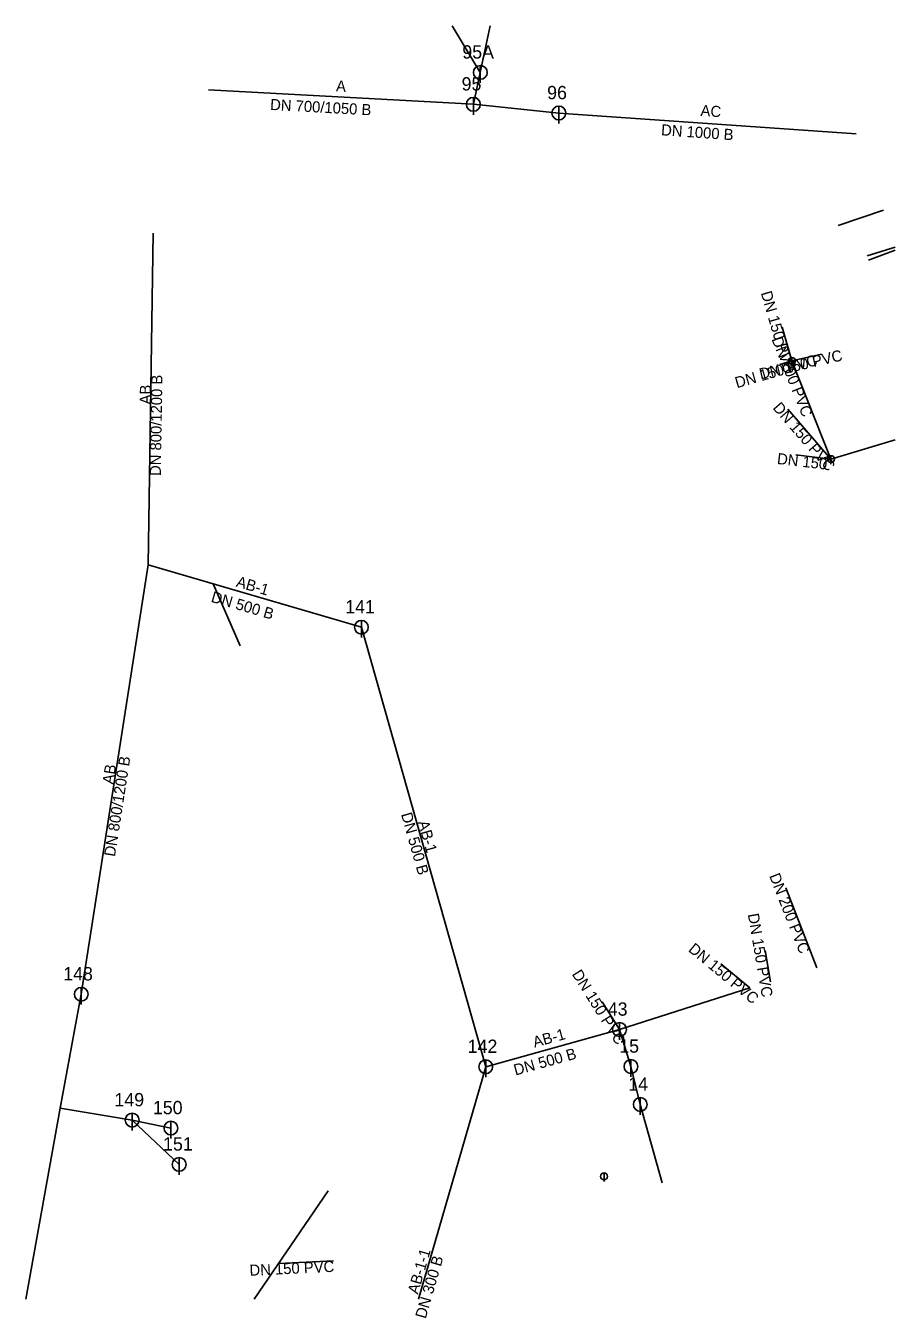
# Model space of a CAD drawing. Extents: x -444516 to -444390, y -1121153 to -1120965.
import ezdxf

# ---------------------------------------------------------------- set-up
doc = ezdxf.new("R2010")
doc.units = 0
for name, color, linetype in [('_pripojka_kanal_destova_priblizne_', 7, 'Continuous'), ('_pripojka_kanal_jednotna_priblizne_', 7, 'Continuous'), ('_pripojka_kanal_splaskova_priblizne_', 7, 'Continuous'), ('_stoka_jednotna_smvak_prevzato_z_dokumentace_', 7, 'Continuous'), ('Default', 7, 'Continuous'), ('MoLevel 119', 7, 'Continuous'), ('MoLevel 120', 7, 'Continuous'), ('MoLevel 124', 7, 'Continuous'), ('MoLevel 128', 7, 'Continuous'), ('MoLevel 57', 7, 'Continuous'), ('MoLevel 60', 7, 'Continuous'), ('MoLevel 68', 7, 'Continuous'), ('MoLevel 69', 7, 'Continuous')]:
    doc.layers.add(name, color=color, linetype=linetype)

# ---------------------------------------------------------------- blocks, each defined once
blk = doc.blocks.new('_sachta_kanal_prip_')
at = {"layer": 'Default'}
blk.add_line((0, 0.00005), (0, -0.000075), dxfattribs=at)
blk.add_circle((0, 0), 0.00005, dxfattribs=at)
blk = doc.blocks.new('_sachta_kanal_prevzato_z_dokumentace_')
at = {"layer": 'Default'}
blk.add_line((0, 0.00005), (0, -0.000075), dxfattribs=at)
blk.add_circle((0, 0), 0.00005, dxfattribs=at)

msp = doc.modelspace()

# ---------------------------------------------------------------- linework, layer by layer
at = {"layer": '_pripojka_kanal_destova_priblizne_'}
for p, q in [((-444453.97, -1120965.24), (-444449.9, -1120971.98)), ((-444405.37, -1121020.79), (-444399.11, -1121028.01))]:
    msp.add_line(p, q, dxfattribs=at)
at = {"layer": '_pripojka_kanal_jednotna_priblizne_'}
for p, q in [((-444398.04, -1120994.19), (-444391.52, -1120991.95)), ((-444393.86, -1120998.56), (-444389.81, -1120997.31)), ((-444393.69, -1120999.17), (-444389.81, -1120997.76)), ((-444399.11, -1121028.01), (-444389.81, -1121025.21)), ((-444484.67, -1121055.09), (-444488.59, -1121046.11)), ((-444405.66, -1121090.17), (-444401.13, -1121101.74)), ((-444408.63, -1121099.25), (-444407.86, -1121103.76)), ((-444415.04, -1121101.17), (-444410.85, -1121104.65)), ((-444432.26, -1121106.67), (-444429.74, -1121110.68)), ((-444471.95, -1121134.05), (-444482.65, -1121149.76)), ((-444471.15, -1121144.19), (-444479.12, -1121144.57))]:
    msp.add_line(p, q, dxfattribs=at)
at = {"layer": '_pripojka_kanal_splaskova_priblizne_'}
for p, q in [((-444406.17, -1121008.92), (-444404.76, -1121013.79)), ((-444400.5, -1121012.8), (-444404.76, -1121013.79)), ((-444406.5, -1121014.29), (-444404.76, -1121013.79)), ((-444404.76, -1121013.79), (-444399.11, -1121028.01)), ((-444404.21, -1121027.42), (-444399.11, -1121028.01))]:
    msp.add_line(p, q, dxfattribs=at)
at = {"layer": '_stoka_jednotna_smvak_prevzato_z_dokumentace_'}
for p, q in [((-444448.46, -1120965.24), (-444449.9, -1120971.98)), ((-444449.9, -1120971.98), (-444450.91, -1120976.61)), ((-444450.91, -1120976.61), (-444489.29, -1120974.53)), ((-444438.52, -1120977.87), (-444450.91, -1120976.61)), ((-444395.45, -1120980.88), (-444438.52, -1120977.87)), ((-444498.04, -1121043.34), (-444497.27, -1120995.3)), ((-444507.71, -1121105.57), (-444498.04, -1121043.34)), ((-444467.13, -1121052.39), (-444498.04, -1121043.34)), ((-444449.12, -1121116.07), (-444467.13, -1121052.39)), ((-444410.85, -1121104.65), (-444429.74, -1121110.68)), ((-444510.74, -1121122.07), (-444507.71, -1121105.57)), ((-444429.74, -1121110.68), (-444449.12, -1121116.07)), ((-444428.08, -1121116.04), (-444429.74, -1121110.68)), ((-444458.88, -1121149.76), (-444449.12, -1121116.07)), ((-444426.73, -1121121.54), (-444428.08, -1121116.04)), ((-444423.57, -1121132.89), (-444426.73, -1121121.54)), ((-444515.73, -1121149.76), (-444510.74, -1121122.07)), ((-444500.33, -1121123.81), (-444510.74, -1121122.07)), ((-444494.72, -1121124.96), (-444500.33, -1121123.81)), ((-444493.52, -1121130.23), (-444500.33, -1121123.81))]:
    msp.add_line(p, q, dxfattribs=at)

# ---------------------------------------------------------------- block references
at = {"layer": 'MoLevel 119', "xscale": 20000, "yscale": 20000}
for p in [(-444449.9, -1120971.98), (-444450.91, -1120976.61), (-444438.52, -1120977.87), (-444467.13, -1121052.39), (-444507.71, -1121105.57), (-444429.74, -1121110.68), (-444449.12, -1121116.07), (-444428.08, -1121116.04), (-444426.73, -1121121.54), (-444500.33, -1121123.81), (-444494.72, -1121124.96), (-444493.52, -1121130.23)]:
    msp.add_blockref('_sachta_kanal_prevzato_z_dokumentace_', p, dxfattribs=at)
at = {"layer": 'MoLevel 57', "xscale": 10000, "yscale": 10000}
for p in [(-444404.76, -1121013.79), (-444399.11, -1121028.01), (-444431.97, -1121131.96)]:
    msp.add_blockref('_sachta_kanal_prip_', p, dxfattribs=at)

# ---------------------------------------------------------------- texts
at = {"layer": 'MoLevel 120'}
for s, p in [('95A', (-444452.51, -1120969.98)), ('95', (-444452.61, -1120974.61)), ('96', (-444440.22, -1120975.87)), ('141', (-444469.47, -1121050.39)), ('148', (-444510.32, -1121103.57)), ('43', (-444431.44, -1121108.68)), ('142', (-444451.73, -1121114.07)), ('15', (-444429.78, -1121114.04)), ('14', (-444428.47, -1121119.54)), ('149', (-444502.9, -1121121.81)), ('150', (-444497.33, -1121122.96)), ('151', (-444495.86, -1121128.23))]:
    msp.add_text(s, height=1.926, dxfattribs=at).set_placement(p)
at = {"layer": 'MoLevel 124'}
for s, rotation, p in [('DN 200 PVC', 291.3962, (-444408.08, -1121088.41)), ('DN 150 PVC', 279.6587, (-444411.16, -1121093.98)), ('DN 150 PVC', 320.3376, (-444419.88, -1121099.25)), ('DN 150 PVC', 302.1772, (-444436.69, -1121102.65)), ('DN 150 PVC', 2.7312, (-444483.3, -1121146.38))]:
    msp.add_text(s, height=1.605, rotation=rotation, dxfattribs=at).set_placement(p)
at = {"layer": 'MoLevel 128'}
msp.add_text('DN 150 PVC', height=1.605, rotation=310.9036, dxfattribs=at).set_placement((-444407.62, -1121020.64))
at = {"layer": 'MoLevel 60'}
for s, rotation, p in [('DN 150 PVC', 286.1441, (-444409.28, -1121003.93)), ('DN 200 PVC', 291.648, (-444407.74, -1121010.64)), ('DN 150 PVC', 16.0677, (-444412.74, -1121017.76)), ('DN 150 PVC', 13.0949, (-444409.29, -1121016.49)), ('DN 150', 353.4139, (-444406.98, -1121028.72))]:
    msp.add_text(s, height=1.605, rotation=rotation, dxfattribs=at).set_placement(p)
at = {"layer": 'MoLevel 68'}
for s, height, rotation, p in [('DN 700/1050 B', 1.6049, 356.8979, (-444480.38, -1120977.42)), ('DN 1000 B', 1.605, 356.0023, (-444423.75, -1120981.09)), ('DN 800/1200 B', 1.6049, 89.0869, (-444496.18, -1121030.48)), ('DN 500 B', 1.605, 343.6802, (-444489.02, -1121048.68)), ('DN 800/1200 B', 1.6049, 81.1671, (-444502.83, -1121085.7)), ('DN 500 B', 1.605, 285.792, (-444461.4, -1121079.48)), ('DN 500 B', 1.605, 15.5424, (-444444.81, -1121117.36)), ('DN 300 B', 1.605, 73.8462, (-444457.82, -1121152.68))]:
    msp.add_text(s, height=height, rotation=rotation, dxfattribs=at).set_placement(p)
at = {"layer": 'MoLevel 69'}
for s, height, rotation, p in [('A', 1.6, 356.8979, (-444470.83, -1120974.73)), ('AC', 1.605, 356.0023, (-444418.04, -1120978.28)), ('AB', 1.605, 89.0869, (-444497.65, -1121020.11)), ('AB-1', 1.605, 343.6802, (-444485.38, -1121046.47)), ('AB', 1.605, 81.1671, (-444503.08, -1121075.21)), ('AB-1', 1.605, 285.792, (-444458.96, -1121080.64)), ('AB-1', 1.605, 15.5424, (-444442.04, -1121113.32)), ('AB-1-1', 1.605, 73.8462, (-444458.93, -1121149.13))]:
    msp.add_text(s, height=height, rotation=rotation, dxfattribs=at).set_placement(p)

doc.saveas('drawing.dxf')
